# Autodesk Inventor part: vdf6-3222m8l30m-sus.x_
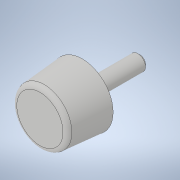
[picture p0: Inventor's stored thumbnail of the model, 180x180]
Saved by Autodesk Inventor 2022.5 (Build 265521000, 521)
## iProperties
Created: 2021-08
Part Number: vdf6-3222m8l30m-sus.x_
Material: 一般
Document SubType Name: Modeling
Designer: ImaoCorp
Density: 1 g/cm^3
Appearance: 既定
Sending System: SOLIDWORKS 2019-2019304
MC: AMD64
MC_MODEL: Intel64 Family 6 Model 60 Stepping 3, GenuineIntel
OS: Windows_NT
FRU: Parasolid Version 31.0, build 290,  9- 1-2019
FORMAT: text
GUISE: transmit
KEY: vdf6-3222m8l30m-sus
FILE: vdf6-3222m8l30m-sus.x_t
DATE: Wed Aug 11 14:58:57 2021
Author: ImaoCorp
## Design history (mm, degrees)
feature "Base1"
node "ソリッド1"
